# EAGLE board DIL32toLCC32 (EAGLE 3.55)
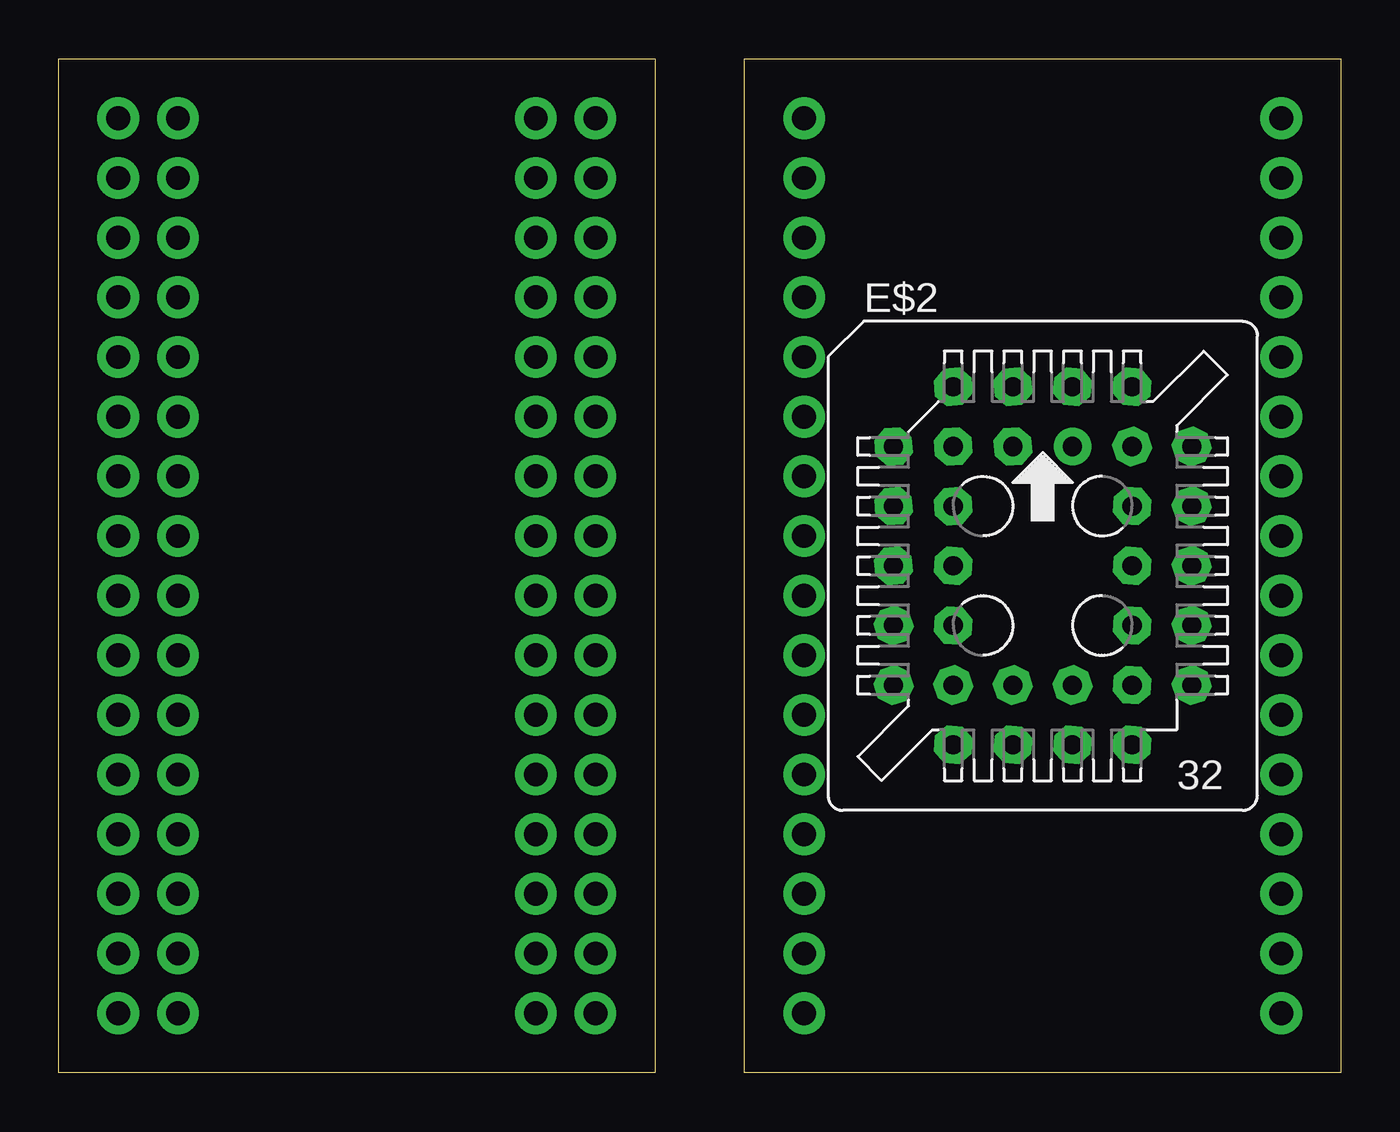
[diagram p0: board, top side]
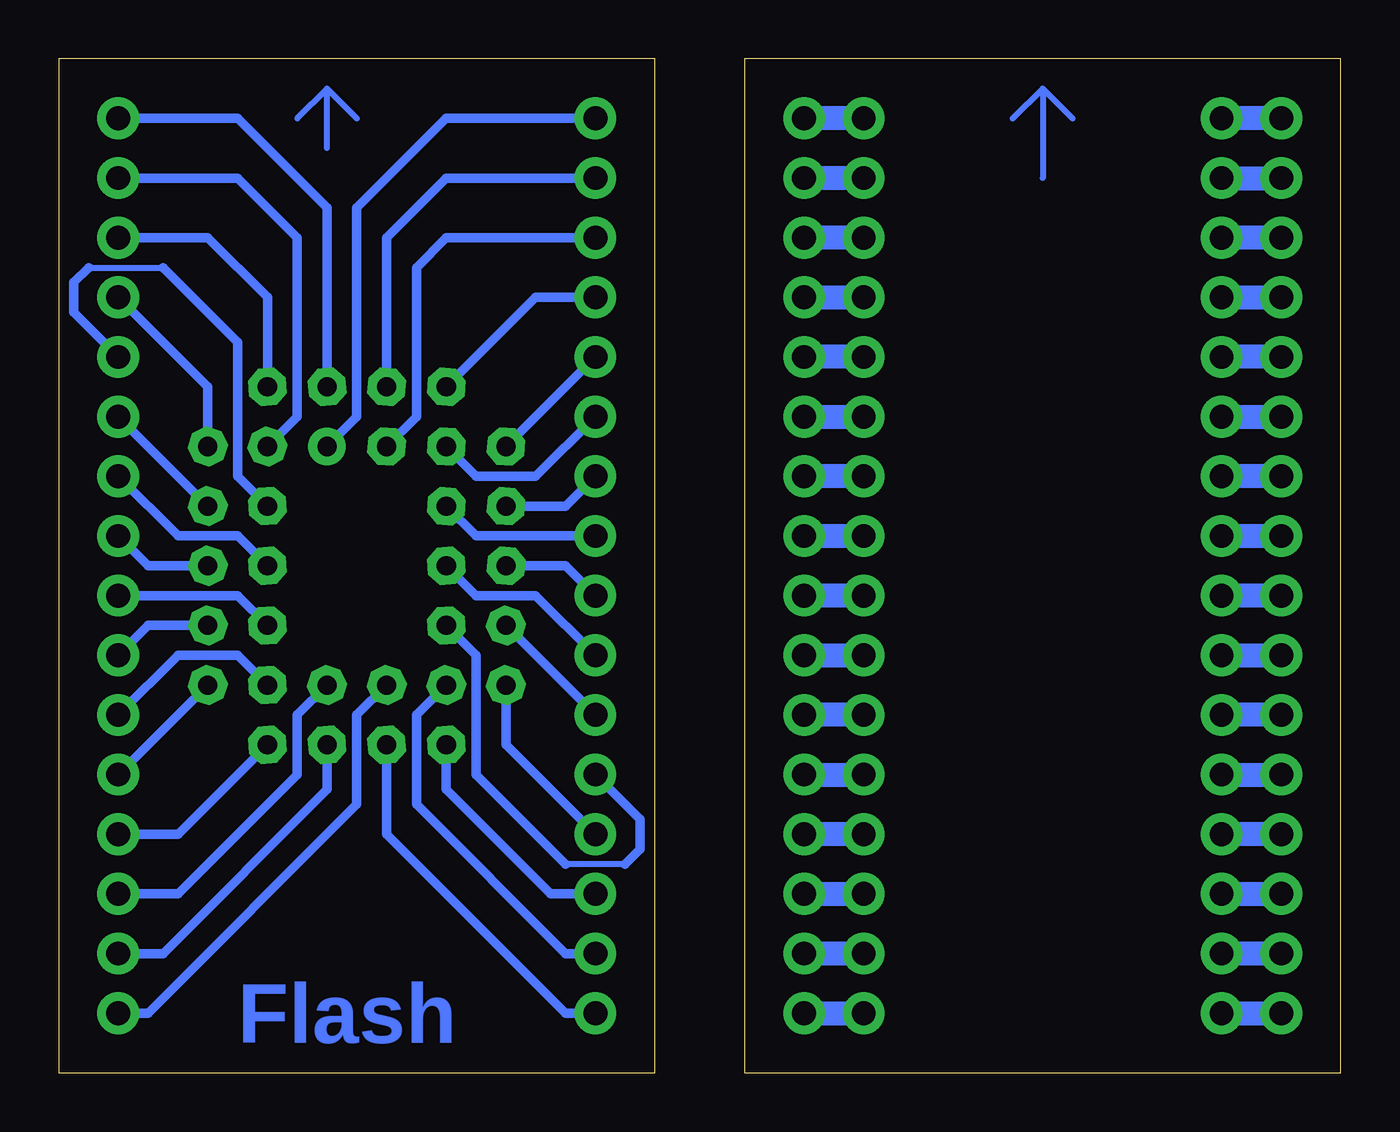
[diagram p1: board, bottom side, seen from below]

Size 54.61 x 43.18 mm. Coordinates in mm from the lower left corner, seen from the top.
Outline: 25.4,43.18 25.4,0 0,0 0,43.18 25.4,43.18
Outline: 29.21,43.18 54.61,43.18 54.61,0 29.21,0 29.21,43.18
Copper layers used: Bottom

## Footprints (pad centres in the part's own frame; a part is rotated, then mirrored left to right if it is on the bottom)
AD10 = drill 1.016 pad 1.778 round:  0,0
2 = drill 0.813 pad 1.6 round:  1.27,5.08 | drill 0.813 pad 1.6 octagon:  -1.27,7.62;  -1.27,5.08;  -3.81,7.62;  -6.35,5.08;  -3.81,5.08;  -6.35,2.54;  -3.81,2.54;  -6.35,0;  -3.81,0;  -6.35,-2.54;  -3.81,-2.54;  -6.35,-5.08;  -3.81,-7.62;  -3.81,-5.08;  -1.27,-7.62;  -1.27,-5.08;  1.27,-7.62;  1.27,-5.08;  3.81,-7.62;  6.35,-5.08;  3.81,-5.08;  6.35,-2.54;  3.81,-2.54;  6.35,0;  3.81,0;  6.35,2.54;  3.81,2.54;  6.35,5.08;  3.81,7.62;  3.81,5.08;  1.27,7.62

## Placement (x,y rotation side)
E$1  [AD10]  31.75,40.64 0 top
E$2  [2]  41.91,21.59 0 top
E$3  [AD10]  2.54,40.64 0 top
E$4  [AD10]  2.54,38.1 0 top
E$5  [AD10]  2.54,35.56 0 top
E$6  [AD10]  2.54,33.02 0 top
E$7  [AD10]  2.54,30.48 0 top
E$8  [AD10]  2.54,27.94 0 top
E$9  [AD10]  2.54,25.4 0 top
E$10  [AD10]  2.54,22.86 0 top
E$11  [AD10]  2.54,20.32 0 top
E$12  [AD10]  2.54,17.78 0 top
E$13  [AD10]  2.54,15.24 0 top
E$14  [AD10]  2.54,12.7 0 top
E$15  [AD10]  2.54,10.16 0 top
E$16  [AD10]  2.54,7.62 0 top
E$17  [AD10]  2.54,5.08 0 top
E$18  [AD10]  2.54,2.54 0 top
E$19  [AD10]  22.86,40.64 0 top
E$20  [AD10]  22.86,38.1 0 top
E$21  [AD10]  22.86,35.56 0 top
E$22  [AD10]  22.86,33.02 0 top
E$23  [AD10]  22.86,30.48 0 top
E$24  [AD10]  22.86,27.94 0 top
E$25  [AD10]  22.86,25.4 0 top
E$26  [AD10]  22.86,22.86 0 top
E$27  [AD10]  22.86,20.32 0 top
E$28  [AD10]  22.86,17.78 0 top
E$29  [AD10]  22.86,15.24 0 top
E$30  [AD10]  22.86,12.7 0 top
E$31  [AD10]  22.86,10.16 0 top
E$32  [AD10]  22.86,7.62 0 top
E$33  [AD10]  22.86,5.08 0 top
E$34  [AD10]  22.86,2.54 0 top
E$35  [AD10]  5.08,40.64 0 top
E$36  [AD10]  5.08,38.1 0 top
E$37  [AD10]  5.08,35.56 0 top
E$38  [AD10]  5.08,33.02 0 top
E$39  [AD10]  5.08,30.48 0 top
E$40  [AD10]  5.08,27.94 0 top
E$41  [AD10]  5.08,25.4 0 top
E$42  [AD10]  5.08,22.86 0 top
E$43  [AD10]  5.08,20.32 0 top
E$44  [AD10]  5.08,17.78 0 top
E$45  [AD10]  5.08,15.24 0 top
E$46  [AD10]  5.08,12.7 0 top
E$47  [AD10]  5.08,10.16 0 top
E$48  [AD10]  5.08,7.62 0 top
E$49  [AD10]  5.08,5.08 0 top
E$50  [AD10]  5.08,2.54 0 top
E$51  [AD10]  20.32,40.64 0 top
E$52  [AD10]  20.32,38.1 0 top
E$53  [AD10]  20.32,35.56 0 top
E$54  [AD10]  20.32,33.02 0 top
E$55  [AD10]  20.32,30.48 0 top
E$56  [AD10]  20.32,27.94 0 top
E$57  [AD10]  20.32,25.4 0 top
E$58  [AD10]  20.32,22.86 0 top
E$59  [AD10]  20.32,20.32 0 top
E$60  [AD10]  20.32,17.78 0 top
E$61  [AD10]  20.32,15.24 0 top
E$62  [AD10]  20.32,12.7 0 top
E$63  [AD10]  20.32,10.16 0 top
E$64  [AD10]  20.32,7.62 0 top
E$65  [AD10]  20.32,5.08 0 top
E$66  [AD10]  20.32,2.54 0 top
E$67  [AD10]  31.75,38.1 0 top
E$68  [AD10]  31.75,35.56 0 top
E$69  [AD10]  31.75,33.02 0 top
E$70  [AD10]  31.75,30.48 0 top
E$71  [AD10]  31.75,27.94 0 top
E$72  [AD10]  31.75,25.4 0 top
E$73  [AD10]  31.75,22.86 0 top
E$74  [AD10]  31.75,20.32 0 top
E$75  [AD10]  31.75,17.78 0 top
E$76  [AD10]  31.75,15.24 0 top
E$77  [AD10]  31.75,12.7 0 top
E$78  [AD10]  31.75,10.16 0 top
E$79  [AD10]  31.75,7.62 0 top
E$80  [AD10]  31.75,5.08 0 top
E$81  [AD10]  31.75,2.54 0 top
E$82  [AD10]  52.07,40.64 0 top
E$83  [AD10]  52.07,38.1 0 top
E$84  [AD10]  52.07,35.56 0 top
E$85  [AD10]  52.07,33.02 0 top
E$86  [AD10]  52.07,30.48 0 top
E$87  [AD10]  52.07,27.94 0 top
E$88  [AD10]  52.07,25.4 0 top
E$89  [AD10]  52.07,22.86 0 top
E$90  [AD10]  52.07,20.32 0 top
E$91  [AD10]  52.07,17.78 0 top
E$92  [AD10]  52.07,15.24 0 top
E$93  [AD10]  52.07,12.7 0 top
E$94  [AD10]  52.07,10.16 0 top
E$95  [AD10]  52.07,7.62 0 top
E$96  [AD10]  52.07,5.08 0 top
E$97  [AD10]  52.07,2.54 0 top

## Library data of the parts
E$1 E$3-E$97 = holgnorm
E$2 = plccpack

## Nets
S$1: E$3. E$35.
S$2: E$4. E$36.
S$3: E$5. E$37.
S$4: E$6. E$38.
S$5: E$7. E$39.
S$6: E$8. E$40.
S$7: E$9. E$41.
S$8: E$10. E$42.
S$9: E$11. E$43.
S$10: E$12. E$44.
S$11: E$13. E$45.
S$12: E$14. E$46.
S$13: E$15. E$47.
S$14: E$16. E$48.
S$15: E$17. E$49.
S$16: E$18. E$50.
S$17: E$19. E$51.
S$18: E$20. E$52.
S$19: E$21. E$53.
S$20: E$22. E$54.
S$21: E$23. E$55.
S$22: E$24. E$56.
S$23: E$25. E$57.
S$24: E$26. E$58.
S$25: E$27. E$59.
S$26: E$28. E$60.
S$27: E$29. E$61.
S$28: E$30. E$62.
S$29: E$31. E$63.
S$30: E$32. E$64.
S$31: E$33. E$65.
S$32: E$34. E$66.
S$33: E$1. E$2.
S$34: E$2. E$67.
S$35: E$2. E$68.
S$36: E$2. E$69.
S$37: E$2. E$70.
S$38: E$2. E$71.
S$39: E$2. E$72.
S$40: E$2. E$73.
S$41: E$2. E$74.
S$42: E$2. E$75.
S$43: E$2. E$76.
S$44: E$2. E$77.
S$45: E$2. E$78.
S$46: E$2. E$79.
S$47: E$2. E$80.
S$48: E$2. E$81.
S$49: E$2. E$97.
S$50: E$2. E$96.
S$51: E$2. E$95.
S$52: E$2. E$94.
S$53: E$2. E$93.
S$54: E$2. E$92.
S$55: E$2. E$91.
S$56: E$2. E$90.
S$57: E$2. E$89.
S$58: E$2. E$88.
S$59: E$2. E$87.
S$60: E$2. E$86.
S$61: E$2. E$85.
S$62: E$2. E$84.
S$63: E$2. E$83.
S$64: E$2. E$82.

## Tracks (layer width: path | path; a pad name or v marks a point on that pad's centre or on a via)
S$1
  Bottom 1.016: E$3. E$35.
S$2
  Bottom 1.016: E$36. E$4.
S$3
  Bottom 1.016: E$5. E$37.
S$4
  Bottom 1.016: E$38. E$6.
S$5
  Bottom 1.016: E$7. E$39.
S$6
  Bottom 1.016: E$40. E$8.
S$7
  Bottom 1.016: E$9. E$41.
S$8
  Bottom 1.016: E$42. E$10.
S$9
  Bottom 1.016: E$11. E$43.
S$10
  Bottom 1.016: E$44. E$12.
S$11
  Bottom 1.016: E$13. E$45.
S$12
  Bottom 1.016: E$46. E$14.
S$13
  Bottom 1.016: E$15. E$47.
S$14
  Bottom 1.016: E$48. E$16.
S$15
  Bottom 1.016: E$17. E$49.
S$16
  Bottom 1.016: E$50. E$18.
S$17
  Bottom 1.016: E$51. E$19.
S$18
  Bottom 1.016: E$52. E$20.
S$19
  Bottom 1.016: E$53. E$21.
S$20
  Bottom 1.016: E$22. E$54.
S$21
  Bottom 1.016: E$55. E$23.
S$22
  Bottom 1.016: E$24. E$56.
S$23
  Bottom 1.016: E$57. E$25.
S$24
  Bottom 1.016: E$26. E$58.
S$25
  Bottom 1.016: E$59. E$27.
S$26
  Bottom 1.016: E$28. E$60.
S$27
  Bottom 1.016: E$61. E$29.
S$28
  Bottom 1.016: E$30. E$62.
S$29
  Bottom 1.016: E$63. E$31.
S$30
  Bottom 1.016: E$32. E$64.
S$31
  Bottom 1.016: E$65. E$33.
S$32
  Bottom 1.016: E$34. E$66.
S$33
  Bottom 0.406: 43.18,26.67 41.91,27.94 41.91,36.83 38.1,40.64 E$1.
S$34
  Bottom 0.406: E$67. 38.1,38.1 40.64,35.56 40.64,29.21
S$35
  Bottom 0.406: E$68. 38.1,35.56 39.37,34.29 39.37,27.94 40.64,26.67
S$36
  Bottom 0.406: E$69. 34.29,33.02 38.1,29.21
S$37
  Bottom 0.406: E$70. 35.56,26.67
S$38
  Bottom 0.406: E$71. 34.29,25.4 36.83,25.4 38.1,26.67
S$39
  Bottom 0.406: E$72. 33.02,24.13 35.56,24.13
S$40
  Bottom 0.406: E$73. 36.83,22.86 38.1,24.13
S$41
  Bottom 0.406: E$74. 33.02,21.59 35.56,21.59
S$42
  Bottom 0.406: E$75. 34.29,20.32 36.83,20.32 38.1,21.59
S$43
  Bottom 0.406: E$76. 35.56,19.05
S$44
  Bottom 0.254: 30.48,8.89 33.02,8.89
  Bottom 0.406: E$77. 29.84,10.79 29.84,9.53 30.48,8.89 | 33.02,8.89 36.83,12.7 36.83,17.78 38.1,19.05
S$45
  Bottom 0.406: E$78. 35.56,13.97 35.56,16.51
S$46
  Bottom 0.406: E$79. 33.65,7.62 38.1,12.07 38.1,13.97
S$47
  Bottom 0.406: E$80. 33.02,5.08 39.37,11.43 39.37,15.24 38.1,16.51
S$48
  Bottom 0.406: E$81. 33.02,2.54 40.64,10.16 40.64,13.97
S$49
  Bottom 0.406: E$97. 50.8,2.54 41.91,11.43 41.91,15.24 40.64,16.51
S$50
  Bottom 0.406: E$96. 50.16,5.08 43.18,12.07 43.18,13.97
S$51
  Bottom 0.406: E$95. 49.53,7.62 44.45,12.7 44.45,15.24 43.18,16.51
S$52
  Bottom 0.406: E$94. 49.53,10.16 45.72,13.97
S$53
  Bottom 0.406: E$93. 48.26,16.51
S$54
  Bottom 0.406: 45.72,16.51 46.99,17.78 49.53,17.78 E$92.
S$55
  Bottom 0.406: E$91. 50.8,19.05 48.26,19.05
S$56
  Bottom 0.406: E$90. 46.99,20.32 45.72,19.05
S$57
  Bottom 0.406: E$89. 50.8,21.59 48.26,21.59
S$58
  Bottom 0.406: E$88. 49.53,22.86 46.99,22.86 45.72,21.59
S$59
  Bottom 0.406: E$87. 48.26,24.13
S$60
  Bottom 0.254: 53.34,34.29 50.16,34.29
  Bottom 0.406: E$86. 53.97,32.38 53.97,33.65 53.34,34.29 | 50.16,34.29 46.99,31.11 46.99,25.4 45.72,24.13
S$61
  Bottom 0.406: E$85. 48.26,29.21 48.26,26.67
S$62
  Bottom 0.406: E$84. 48.26,35.56 45.72,33.02 45.72,29.21
S$63
  Bottom 0.406: E$83. 46.99,38.1 44.45,35.56 44.45,27.94 45.72,26.67
S$64
  Bottom 0.406: E$2. 43.18,36.83 46.99,40.64 E$82.
S$65
  Bottom 0.254: 43.18,39.37 43.18,41.91 | 43.18,41.91 41.91,40.64 | 43.18,41.91 44.45,40.64
S$66
  Bottom 0.254: 12.7,41.91 12.7,38.1 | 12.7,41.91 11.43,40.64 | 12.7,41.91 13.97,40.64

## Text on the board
Bottom: Flash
